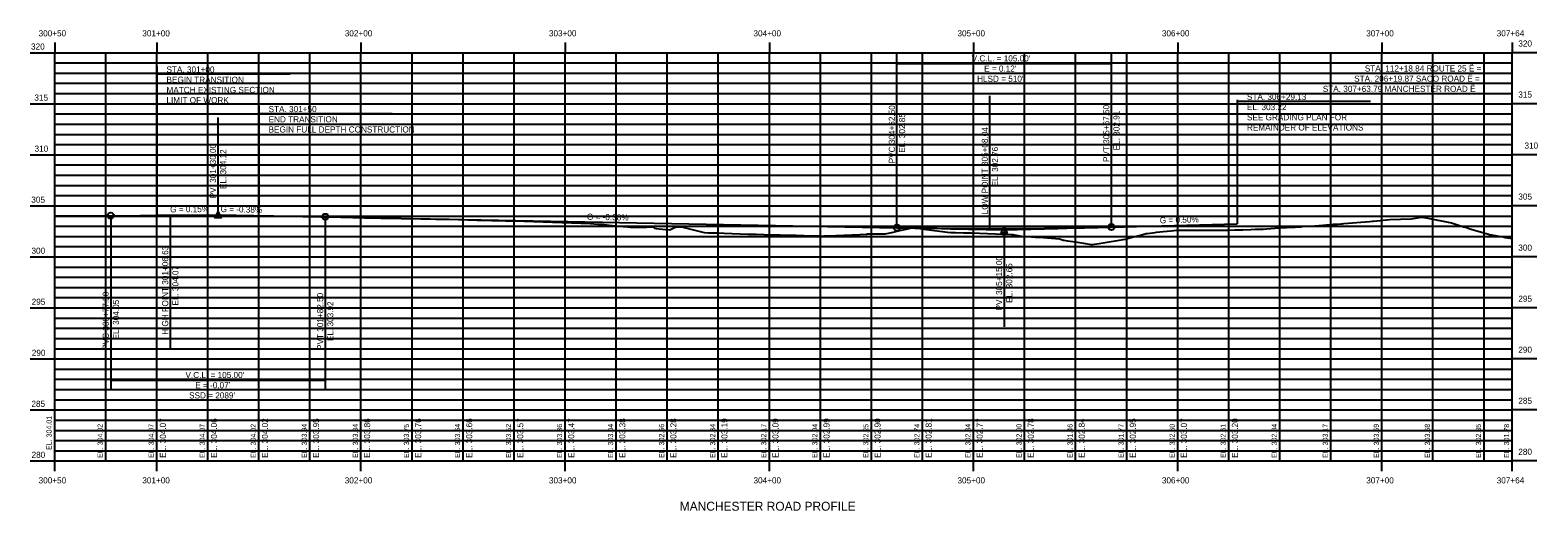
# Model space of a CAD drawing. Extents: x 916064 to 2216531, y 210276 to 327856.
# Drawn here: x 917779 to 918517, y 326079 to 326315 of the extents above; entities that cross this region are included whole.
import ezdxf

# ---------------------------------------------------------------- set-up
doc = ezdxf.new("R2010")
doc.units = 0
for name, color, linetype in [('ANNOTATION', 7, 'Continuous'), ('BARRIER', 7, 'Continuous'), ('D_Roadway_Centerline', 7, 'Continuous'), ('D_Roadway_Centerline_Bearings', 7, 'Continuous'), ('D_Roadway_Centerline_CurveData', 7, 'Continuous'), ('D_Roadway_Centerline_Flags', 7, 'Continuous'), ('D_Roadway_Centerline_Text', 7, 'Continuous'), ('D_Roadway_Edge_Pavement', 7, 'Continuous')]:
    doc.layers.add(name, color=color, linetype=linetype)

msp = doc.modelspace()

# ---------------------------------------------------------------- linework, layer by layer
at = {"layer": 'ANNOTATION'}
for p, q in [((917923.54, 326223.12), (918203.54, 326217.76)), ((918308.54, 326218.07), (918370.17, 326219.61))]:
    msp.add_line(p, q, dxfattribs=at)
for points in [[(917841.04, 326223.84), (917842.6, 326223.85), (917844.79, 326223.85), (917846.97, 326223.85), (917849.16, 326223.85), (917851.35, 326223.85), (917853.54, 326223.84), (917855.72, 326223.84), (917857.91, 326223.84), (917860.1, 326223.83), (917862.29, 326223.82), (917864.47, 326223.81), (917866.66, 326223.8), (917868.85, 326223.79), (917873.22, 326223.77), (917875.41, 326223.75), (917877.6, 326223.74), (917879.79, 326223.72), (917881.97, 326223.7), (917884.16, 326223.68), (917886.35, 326223.66), (917888.54, 326223.64), (917890.72, 326223.62), (917892.91, 326223.59), (917895.1, 326223.57), (917897.29, 326223.54), (917899.47, 326223.51), (917901.66, 326223.48), (917903.85, 326223.45), (917906.04, 326223.42), (917908.22, 326223.39), (917910.41, 326223.35), (917912.6, 326223.32), (917914.79, 326223.28), (917916.97, 326223.24), (917919.16, 326223.2), (917921.35, 326223.16), (917923.54, 326223.12)], [(918203.54, 326217.76), (918205.72, 326217.72), (918207.91, 326217.68), (918210.1, 326217.65), (918212.29, 326217.61), (918214.47, 326217.58), (918216.66, 326217.55), (918218.85, 326217.52), (918221.04, 326217.49), (918223.22, 326217.47), (918225.41, 326217.44), (918227.6, 326217.42), (918229.79, 326217.4), (918231.97, 326217.39), (918234.16, 326217.37), (918236.35, 326217.36), (918238.54, 326217.35), (918240.72, 326217.34), (918242.91, 326217.33), (918245.1, 326217.33), (918247.29, 326217.33), (918249.47, 326217.33), (918251.66, 326217.33), (918253.85, 326217.33), (918258.22, 326217.34), (918260.41, 326217.35), (918262.6, 326217.36), (918264.79, 326217.38), (918266.97, 326217.39), (918269.16, 326217.41), (918271.35, 326217.43), (918273.54, 326217.45), (918275.72, 326217.48), (918277.91, 326217.5), (918280.1, 326217.53), (918282.29, 326217.56), (918284.47, 326217.59), (918286.66, 326217.62), (918288.85, 326217.66), (918291.04, 326217.7), (918293.22, 326217.74), (918295.41, 326217.78), (918297.6, 326217.82), (918299.79, 326217.87), (918301.97, 326217.91), (918304.16, 326217.96), (918306.35, 326218.02), (918308.54, 326218.07)]]:
    msp.add_lwpolyline(points, dxfattribs=at)
at = {"layer": 'D_Roadway_Centerline'}
for p, q in [((917791.04, 326308.51), (917791.04, 326303.51)), ((917841.04, 326308.51), (917841.04, 326303.51)), ((917941.04, 326308.51), (917941.04, 326303.51)), ((918041.04, 326308.51), (918041.04, 326303.51)), ((918141.04, 326308.51), (918141.04, 326303.51)), ((918241.04, 326308.51), (918241.04, 326303.51)), ((918341.04, 326308.51), (918341.04, 326303.51)), ((918441.04, 326308.51), (918441.04, 326303.51)), ((918504.83, 326308.51), (918504.83, 326303.51)), ((917779.04, 326303.51), (917791.04, 326303.51)), ((917779.04, 326303.51), (917791.04, 326303.51)), ((917791.04, 326303.51), (918504.83, 326303.51)), ((917791.04, 326103.51), (917791.04, 326303.51)), ((917841.04, 326103.51), (917841.04, 326303.51)), ((917941.04, 326103.51), (917941.04, 326303.51)), ((918041.04, 326103.51), (918041.04, 326303.51)), ((918141.04, 326103.51), (918141.04, 326303.51)), ((918241.04, 326103.51), (918241.04, 326303.51)), ((918341.04, 326103.51), (918341.04, 326303.51)), ((918441.04, 326103.51), (918441.04, 326303.51)), ((918504.83, 326103.51), (918504.83, 326303.51)), ((918516.83, 326303.51), (918504.83, 326303.51)), ((918516.83, 326303.51), (918504.83, 326303.51)), ((917779.04, 326278.51), (917791.04, 326278.51)), ((917791.04, 326278.51), (918504.83, 326278.51)), ((918516.83, 326278.51), (918504.83, 326278.51)), ((917779.04, 326253.51), (917791.04, 326253.51)), ((917791.04, 326253.51), (918504.83, 326253.51)), ((918516.83, 326253.51), (918504.83, 326253.51)), ((917779.04, 326228.51), (917791.04, 326228.51)), ((917791.04, 326228.51), (918504.83, 326228.51)), ((918516.83, 326228.51), (918504.83, 326228.51)), ((917779.04, 326203.51), (917791.04, 326203.51)), ((917791.04, 326203.51), (918504.83, 326203.51)), ((918516.83, 326203.51), (918504.83, 326203.51)), ((917779.04, 326178.51), (917791.04, 326178.51)), ((917791.04, 326178.51), (918504.83, 326178.51)), ((918516.83, 326178.51), (918504.83, 326178.51)), ((917779.04, 326153.51), (917791.04, 326153.51)), ((917791.04, 326153.51), (918504.83, 326153.51)), ((918516.83, 326153.51), (918504.83, 326153.51)), ((917779.04, 326128.51), (917791.04, 326128.51)), ((917791.04, 326128.51), (918504.83, 326128.51)), ((918516.83, 326128.51), (918504.83, 326128.51)), ((917779.04, 326103.51), (917791.04, 326103.51)), ((917791.04, 326103.51), (918504.83, 326103.51)), ((917791.04, 326098.51), (917791.04, 326103.51)), ((917841.04, 326098.51), (917841.04, 326103.51)), ((917941.04, 326098.51), (917941.04, 326103.51)), ((918041.04, 326098.51), (918041.04, 326103.51)), ((918141.04, 326098.51), (918141.04, 326103.51)), ((918241.04, 326098.51), (918241.04, 326103.51)), ((918341.04, 326098.51), (918341.04, 326103.51)), ((918441.04, 326098.51), (918441.04, 326103.51)), ((918516.83, 326103.51), (918504.83, 326103.51)), ((918504.83, 326098.51), (918504.83, 326103.51))]:
    msp.add_line(p, q, dxfattribs=at)
at = {"layer": 'D_Roadway_Centerline_Bearings'}
for p, q in [((918203.54, 326217.76), (918203.54, 326303.23)), ((918308.54, 326218.07), (918308.54, 326303.23)), ((918203.54, 326242.76), (918203.54, 326290.36)), ((918308.54, 326243.07), (918308.54, 326290.67)), ((918249.07, 326217.33), (918249.07, 326282.33)), ((917871.04, 326224.13), (917871.04, 326271.73)), ((918203.54, 326217.76), (918203.54, 326242.76)), ((918308.54, 326218.07), (918308.54, 326243.07)), ((917818.54, 326223.74), (917818.54, 326198.74)), ((917818.54, 326223.74), (917818.54, 326138.1)), ((917844.79, 326223.94), (917871.04, 326224.13)), ((917847.66, 326223.85), (917847.66, 326158.85)), ((917871.04, 326224.13), (917897.29, 326223.63)), ((917923.54, 326223.12), (917923.54, 326198.12)), ((917923.54, 326223.12), (917923.54, 326138.1)), ((918229.79, 326217.26), (918256.04, 326216.76)), ((918256.04, 326216.76), (918282.29, 326217.41)), ((918256.04, 326216.76), (918256.04, 326169.16)), ((917818.54, 326198.74), (917818.54, 326151.14)), ((917923.54, 326198.12), (917923.54, 326150.52))]:
    msp.add_line(p, q, dxfattribs=at)
for points in [[(918203.54, 326298.22), (918308.54, 326298.22)], [(917818.54, 326143.13), (917923.54, 326143.13)]]:
    msp.add_lwpolyline(points, dxfattribs=at)
for points in [[(917871.04, 326225.63), (917872.54, 326222.63), (917869.54, 326222.63)], [(918256.04, 326218.26), (918257.54, 326215.26), (918254.54, 326215.26)]]:
    msp.add_lwpolyline(points, close=True, dxfattribs=at)
for centre in [(917818.54, 326223.74), (917923.54, 326223.12), (918203.54, 326217.76), (918308.54, 326218.07)]:
    msp.add_circle(centre, 1.5, dxfattribs=at)
at = {"layer": 'D_Roadway_Centerline_Flags'}
msp.add_lwpolyline([(917791.04, 326223.54), (917793.2, 326223.55), (917793.31, 326223.55), (917812.62, 326223.61), (917819.59, 326223.62), (917819.63, 326223.62), (917845.98, 326223.9), (917846.1, 326223.9), (917871, 326223.88), (917871, 326223.88), (917871.26, 326223.87), (917897.75, 326223.54), (917898.3, 326223.54), (917917.79, 326223.19), (917925.23, 326223.03), (917925.43, 326223.03), (917942.7, 326222.65), (917947.31, 326222.55), (917950.76, 326222.48), (917951.18, 326222.48), (917951.91, 326222.47), (917956.52, 326222.41), (917960.62, 326222.37), (917961.13, 326222.36), (917965.74, 326222.27), (917970.35, 326222.17), (917974.96, 326222.07), (917977.69, 326222.01), (917979.56, 326221.99), (917979.84, 326221.98), (917984.17, 326221.88), (917988.78, 326221.77), (917993.39, 326221.66), (917998, 326221.54), (918002.61, 326221.41), (918005.07, 326221.34), (918007.22, 326221.3), (918011.82, 326221.19), (918015.33, 326221.11), (918016.43, 326221.08), (918021.04, 326220.96), (918025.65, 326220.83), (918030.26, 326220.7), (918032.05, 326220.65), (918034.87, 326220.55), (918039.47, 326220.38), (918039.82, 326220.37), (918044.08, 326220.18), (918048.69, 326219.97), (918053.3, 326219.76), (918056.99, 326219.59), (918057.91, 326219.52), (918059.05, 326219.43), (918062.52, 326219.08), (918067.13, 326218.61), (918071.73, 326218.14), (918073.09, 326217.99), (918076.34, 326218.04), (918080.95, 326218.09), (918084.16, 326218.13), (918084.79, 326217.52), (918084.81, 326217.53), (918085.56, 326217.45), (918090.17, 326216.92), (918092.27, 326216.68), (918094.64, 326217.83), (918094.78, 326217.86), (918096.14, 326218.13), (918099.02, 326217.97), (918099.38, 326217.87), (918103.29, 326216.85), (918107.2, 326215.84), (918109.13, 326215.35), (918111.11, 326215.31), (918115.02, 326215.25), (918116.27, 326215.22), (918118.93, 326215.12), (918122.84, 326214.96), (918126.74, 326214.8), (918130.65, 326214.63), (918130.76, 326214.63), (918134.56, 326214.54), (918138.47, 326214.44), (918142.38, 326214.34), (918143.07, 326214.32), (918146.29, 326214.25), (918149.02, 326214.19), (918150.19, 326214.16), (918154.1, 326214.05), (918158.01, 326213.94), (918160.42, 326213.87), (918161.92, 326213.83), (918165.83, 326213.72), (918167, 326213.69), (918167.86, 326213.72), (918169.04, 326213.81), (918169.74, 326213.84), (918173.65, 326214.01), (918177.55, 326214.18), (918181.46, 326214.35), (918185.37, 326214.5), (918188.9, 326214.64), (918188.91, 326214.72), (918189.28, 326214.72), (918193.19, 326214.75), (918197.1, 326214.76), (918197.76, 326214.77), (918201, 326215.47), (918204.91, 326216.33), (918208.82, 326217.2), (918211.51, 326217.8), (918212.73, 326217.64), (918216.64, 326217.12), (918220.55, 326216.61), (918224.46, 326216.11), (918228.36, 326215.61), (918229.95, 326215.41), (918232.27, 326215.39), (918236.18, 326215.34), (918237.23, 326215.33), (918240.09, 326215.23), (918244, 326215.09), (918247.91, 326214.95), (918251.81, 326214.81), (918254.86, 326214.69), (918255.72, 326214.66), (918259.63, 326214.5), (918260.3, 326214.47), (918263.54, 326213.83), (918264.75, 326213.59), (918267.45, 326213.42), (918271.36, 326213.17), (918275.26, 326212.92), (918277.29, 326212.8), (918279.17, 326212.62), (918283.08, 326212.25), (918283.66, 326212.2), (918285.14, 326211.68), (918285.25, 326211.67), (918286.99, 326211.41), (918290.9, 326210.83), (918294.81, 326210.23), (918298.72, 326209.63), (918299.08, 326209.57), (918300.29, 326209.69), (918302.62, 326210.05), (918306.53, 326210.67), (918310.44, 326211.31), (918314.35, 326211.99), (918315.22, 326212.14), (918318.26, 326212.94), (918322.17, 326213.99), (918325.56, 326214.93), (918326.07, 326214.99), (918329.98, 326215.46), (918330.71, 326215.55), (918333.89, 326215.85), (918337.8, 326216.23), (918340.51, 326216.5), (918341.71, 326216.5), (918345.62, 326216.52), (918349.53, 326216.53), (918353.43, 326216.55), (918355.62, 326216.56), (918357.34, 326216.56), (918361.25, 326216.57), (918365.16, 326216.57), (918366.36, 326216.58), (918369.07, 326216.67), (918372.98, 326216.81), (918376.88, 326216.95), (918378.93, 326217.03), (918380.79, 326217.07), (918382.8, 326217.12), (918384.7, 326217.25), (918388.61, 326217.52), (918392.52, 326217.8), (918394.24, 326217.93), (918396.43, 326217.99), (918398.55, 326218.05), (918400.34, 326218.2), (918400.76, 326218.24), (918400.97, 326218.26), (918401.38, 326218.28), (918401.75, 326218.29), (918404.24, 326218.48), (918408.15, 326218.77), (918412.06, 326219.06), (918417.11, 326219.43), (918417.86, 326219.46), (918419.34, 326219.53), (918420.91, 326219.66), (918421.59, 326219.74), (918422.46, 326219.85), (918434.89, 326220.8), (918436.33, 326220.97), (918436.96, 326221.06), (918444.97, 326221.83), (918455.39, 326222.12), (918456.54, 326222.35), (918460.5, 326222.95), (918462.63, 326222.56), (918475.13, 326220.13), (918481.02, 326218.25), (918482.42, 326217.81), (918484.17, 326217.28), (918487.02, 326216.41), (918493.8, 326214.48), (918496.49, 326213.92), (918499.24, 326213.44), (918500.35, 326213.28), (918501.43, 326213.06), (918504.83, 326212.43)], dxfattribs=at)
at = {"layer": 'D_Roadway_Centerline_Text'}
for p, q in [((917791.04, 326298.51), (918504.83, 326298.51)), ((917816.04, 326103.51), (917816.04, 326303.51)), ((917866.04, 326103.51), (917866.04, 326303.51)), ((917891.04, 326103.51), (917891.04, 326303.51)), ((917916.04, 326103.51), (917916.04, 326303.51)), ((917966.04, 326103.51), (917966.04, 326303.51)), ((917991.04, 326103.51), (917991.04, 326303.51)), ((918016.04, 326103.51), (918016.04, 326303.51)), ((918066.04, 326103.51), (918066.04, 326303.51)), ((918091.04, 326103.51), (918091.04, 326303.51)), ((918116.04, 326103.51), (918116.04, 326303.51)), ((918166.04, 326103.51), (918166.04, 326303.51)), ((918191.04, 326103.51), (918191.04, 326303.51)), ((918216.04, 326103.51), (918216.04, 326303.51)), ((918266.04, 326103.51), (918266.04, 326303.51)), ((918291.04, 326103.51), (918291.04, 326303.51)), ((918316.04, 326103.51), (918316.04, 326303.51)), ((918366.04, 326103.51), (918366.04, 326303.51)), ((918391.04, 326103.51), (918391.04, 326303.51)), ((918416.04, 326103.51), (918416.04, 326303.51)), ((918466.04, 326103.51), (918466.04, 326303.51)), ((918491.04, 326103.51), (918491.04, 326303.51)), ((917791.04, 326293.51), (918504.83, 326293.51)), ((917791.04, 326288.51), (918504.83, 326288.51)), ((917791.04, 326283.51), (918504.83, 326283.51)), ((917791.04, 326273.51), (918504.83, 326273.51)), ((917791.04, 326268.51), (918504.83, 326268.51)), ((917791.04, 326263.51), (918504.83, 326263.51)), ((917791.04, 326258.51), (918504.83, 326258.51)), ((917791.04, 326248.51), (918504.83, 326248.51)), ((917791.04, 326243.51), (918504.83, 326243.51)), ((917791.04, 326238.51), (918504.83, 326238.51)), ((917791.04, 326233.51), (918504.83, 326233.51)), ((917791.04, 326223.51), (918504.83, 326223.51)), ((917791.04, 326218.51), (918504.83, 326218.51)), ((917791.04, 326213.51), (918504.83, 326213.51)), ((917791.04, 326208.51), (918504.83, 326208.51)), ((917791.04, 326198.51), (918504.83, 326198.51)), ((917791.04, 326193.51), (918504.83, 326193.51)), ((917791.04, 326188.51), (918504.83, 326188.51)), ((917791.04, 326183.51), (918504.83, 326183.51)), ((917791.04, 326173.51), (918504.83, 326173.51)), ((917791.04, 326168.51), (918504.83, 326168.51)), ((917791.04, 326163.51), (918504.83, 326163.51)), ((917791.04, 326158.51), (918504.83, 326158.51)), ((917791.04, 326148.51), (918504.83, 326148.51)), ((917791.04, 326143.51), (918504.83, 326143.51)), ((917791.04, 326138.51), (918504.83, 326138.51)), ((917791.04, 326133.51), (918504.83, 326133.51)), ((917791.04, 326123.51), (918504.83, 326123.51)), ((917791.04, 326118.51), (918504.83, 326118.51)), ((917791.04, 326113.51), (918504.83, 326113.51)), ((917791.04, 326108.51), (918504.83, 326108.51))]:
    msp.add_line(p, q, dxfattribs=at)
at = {"layer": 'D_Roadway_Edge_Pavement'}
for p, q in [((917841.04, 326296.76), (917841.04, 326223.84)), ((917906.38, 326292.99), (917841.04, 326292.99)), ((918439.48, 326293.51), (918504.83, 326293.51)), ((917891.04, 326277.4), (917891.04, 326228.51)), ((918370.17, 326280.34), (918370.17, 326219.61)), ((918435.51, 326279.59), (918370.17, 326279.59)), ((917956.38, 326273.62), (917891.04, 326273.62))]:
    msp.add_line(p, q, dxfattribs=at)

# ---------------------------------------------------------------- texts
at = {"layer": 'ANNOTATION'}
for s, p in [('LOW POINT 305+08.04', (918248.07, 326224.34)), ('EL. 302.76', (918253.07, 326238)), ('HIGH POINT 301+06.63', (917846.66, 326165.33)), ('EL. 304.07', (917851.66, 326179.63))]:
    msp.add_text(s, height=3, rotation=90, dxfattribs=at).set_placement(p)
at = {"layer": 'BARRIER'}
for s, p in [('EL. 304.07', (917845.54, 326105.01)), ('EL. 304.06', (917870.54, 326105.01)), ('EL. 304.02', (917895.54, 326105.01)), ('EL. 303.95', (917920.54, 326105.01)), ('EL. 303.86', (917945.54, 326105.01)), ('EL. 303.76', (917970.54, 326105.01)), ('EL. 303.66', (917995.54, 326105.01)), ('EL. 303.57', (918020.54, 326105.01)), ('EL. 303.47', (918045.54, 326105.01)), ('EL. 303.38', (918070.54, 326105.01)), ('EL. 303.28', (918095.54, 326105.01)), ('EL. 303.19', (918120.54, 326105.01)), ('EL. 303.09', (918145.54, 326105.01)), ('EL. 302.99', (918170.54, 326105.01)), ('EL. 302.90', (918195.54, 326105.01)), ('EL. 302.81', (918220.54, 326105.01)), ('EL. 302.77', (918245.54, 326105.01)), ('EL. 302.78', (918270.54, 326105.01)), ('EL. 302.84', (918295.54, 326105.01)), ('EL. 302.95', (918320.54, 326105.01)), ('EL. 303.07', (918345.54, 326105.01)), ('EL. 303.20', (918370.54, 326105.01))]:
    msp.add_text(s, height=3, rotation=90, dxfattribs=at).set_placement(p)
at = {"layer": 'D_Roadway_Centerline_Bearings'}
for s, p in [("V.C.L. = 105.00'", (918240.11, 326299.22)), ("E = 0.12'", (918246.2, 326294.22)), ("HLSD = 510'", (918242.77, 326289.22)), ("V.C.L. = 105.00'", (917855.11, 326144.13)), ("E = -0.07'", (917859.89, 326139.13)), ("SSD = 2089'", (917856.87, 326134.13))]:
    msp.add_text(s, height=3, dxfattribs=at).set_placement(p)
for s, rotation, p in [('PVC 304+62.50', 90, (918202.54, 326249.33)), ('PVT 305+67.50', 90, (918307.54, 326249.94)), ('EL. 302.91', 90, (918312.54, 326255.66)), ('EL. 302.85', 90, (918207.54, 326254.51)), ('PVI 301+30.00', 90, (917870.04, 326232.18)), ('EL. 304.12', 90, (917875.04, 326236.73)), ('G = 0.15%', 0.42112, (917847.6, 326225.29)), ('G = -0.38%', 358.90311, (917872.25, 326225.44)), ('G = -0.38%', 358.90311, (918051.66, 326221.67)), ('G = 0.50%', 1.4321, (918332.28, 326219.9)), ('PVI 305+15.00', 90, (918255.04, 326177.24)), ('EL. 302.65', 90, (918260.04, 326180.96)), ('PVC 300+77.50', 90, (917817.54, 326157.98)), ('EL. 304.05', 90, (917822.54, 326163.05)), ('PVT 301+82.50', 90, (917922.54, 326157.9)), ('EL. 303.92', 90, (917927.54, 326162.25))]:
    msp.add_text(s, height=3, rotation=rotation, dxfattribs=at).set_placement(p)
at = {"layer": 'D_Roadway_Centerline_CurveData'}
for s, height, p in [('300+50', 3, (917783.17, 326311.51)), ('301+00', 3, (917833.97, 326311.51)), ('302+00', 3, (917933.11, 326311.51)), ('303+00', 3, (918033.09, 326311.51)), ('304+00', 3, (918133.27, 326311.51)), ('305+00', 3, (918233.17, 326311.51)), ('306+00', 3, (918333.27, 326311.51)), ('307+00', 3, (918433.35, 326311.51)), ('307+64', 3, (918497.25, 326311.51)), ('320', 3, (917779.47, 326305.01)), ('320', 3, (917779.47, 326305.01)), ('320', 3, (918507.83, 326306.51)), ('320', 3, (918507.83, 326306.51)), ('315', 3, (917781.1, 326280.01)), ('315', 3, (918507.83, 326281.51)), ('310', 3, (917781.18, 326255.01)), ('310', 3, (918510.86, 326256.51)), ('305', 3, (917779.61, 326230.01)), ('305', 3, (918507.83, 326231.51)), ('300', 3, (918507.83, 326206.51)), ('300', 3, (917779.69, 326205.01)), ('295', 3, (917779.77, 326180.01)), ('295', 3, (918507.83, 326181.51)), ('290', 3, (917779.85, 326155.01)), ('290', 3, (918507.83, 326156.51)), ('285', 3, (918507.83, 326131.51)), ('285', 3, (917779.66, 326130.01)), ('280', 3, (917779.74, 326105.01)), ('280', 3, (918507.83, 326106.51)), ('300+50', 3, (917783.17, 326092.51)), ('301+00', 3, (917833.97, 326092.51)), ('302+00', 3, (917933.11, 326092.51)), ('303+00', 3, (918033.09, 326092.51)), ('304+00', 3, (918133.27, 326092.51)), ('305+00', 3, (918233.17, 326092.51)), ('306+00', 3, (918333.27, 326092.51)), ('307+00', 3, (918433.35, 326092.51)), ('307+64', 3, (918497.25, 326092.51)), ('MANCHESTER ROAD PROFILE', 4.3749, (918097.16, 326079.14))]:
    msp.add_text(s, height=height, dxfattribs=at).set_placement(p)
at = {"layer": 'D_Roadway_Edge_Pavement'}
for s, p in [('STA. 301+00', (917845.8, 326293.76)), ('STA. 112+18.84 ROUTE 25 Ë =', (918432.66, 326294.29)), ('BEGIN TRANSITION', (917845.8, 326288.76)), ('STA. 206+19.87 SACO ROAD Ë =', (918427.45, 326289.29)), ('MATCH EXISTING SECTION', (917845.8, 326283.76)), ('STA. 306+29.13', (918374.93, 326280.37)), ('STA. 307+63.79 MANCHESTER ROAD Ë', (918412.08, 326284.29)), ('LIMIT OF WORK', (917845.8, 326278.76)), ('STA. 301+50', (917895.8, 326274.4)), ('EL. 303.22', (918374.93, 326275.37)), ('END TRANSITION', (917895.8, 326269.4)), ('BEGIN FULL DEPTH CONSTRUCTION', (917895.8, 326264.4)), ('SEE GRADING PLAN FOR', (918374.93, 326270.37)), ('REMAINDER OF ELEVATIONS', (918374.93, 326265.37))]:
    msp.add_text(s, height=3, dxfattribs=at).set_placement(p)
for s, p in [('EL. 304.01', (917789.54, 326108.92)), ('EL. 304.02', (917814.54, 326105.01)), ('EL. 304.07', (917839.54, 326105.01)), ('EL. 304.07', (917864.54, 326105.01)), ('EL. 304.02', (917889.54, 326105.01)), ('EL. 303.94', (917914.54, 326105.01)), ('EL. 303.84', (917939.54, 326105.01)), ('EL. 303.75', (917964.54, 326105.01)), ('EL. 303.64', (917989.54, 326105.01)), ('EL. 303.52', (918014.54, 326105.01)), ('EL. 303.36', (918039.54, 326105.01)), ('EL. 303.04', (918064.54, 326105.01)), ('EL. 302.66', (918089.54, 326105.01)), ('EL. 302.34', (918114.54, 326105.01)), ('EL. 302.17', (918139.54, 326105.01)), ('EL. 302.04', (918164.54, 326105.01)), ('EL. 302.25', (918189.54, 326105.01)), ('EL. 302.74', (918214.54, 326105.01)), ('EL. 302.34', (918239.54, 326105.01)), ('EL. 302.00', (918264.54, 326105.01)), ('EL. 301.46', (918289.54, 326105.01)), ('EL. 301.77', (918314.54, 326105.01)), ('EL. 302.60', (918339.54, 326105.01)), ('EL. 302.61', (918364.54, 326105.01)), ('EL. 302.84', (918389.54, 326105.01)), ('EL. 303.17', (918414.54, 326105.01)), ('EL. 303.59', (918439.54, 326105.01)), ('EL. 303.68', (918464.54, 326105.01)), ('EL. 302.35', (918489.54, 326105.01)), ('EL. 301.78', (918503.33, 326105.01))]:
    msp.add_text(s, height=2.5, rotation=90, dxfattribs=at).set_placement(p)

doc.saveas('drawing.dxf')
